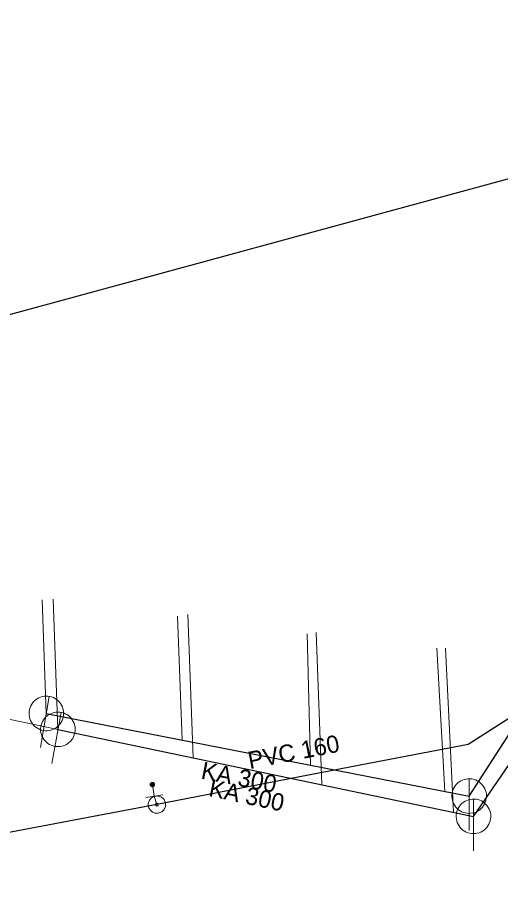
# Model space of a CAD drawing. Extents: x -809028 to -807737, y -990545 to -989489.
# Drawn here: x -808702.15 to -808674.21, y -989756.83 to -989706.95 of the extents above; entities that cross this region are included whole.
import ezdxf

# ---------------------------------------------------------------- set-up
doc = ezdxf.new("R2010")
doc.units = 0
doc.header["$LTSCALE"] = 0.32
for name, color, linetype, lineweight in [('1', 7, 'Continuous', 13), ('11', 7, 'Continuous', 13), ('14', 7, 'Continuous', 25), ('17', 7, 'Continuous', 25), ('22', 7, 'Continuous', 13), ('34', 7, 'Continuous', 13), ('47', 7, 'Continuous', 13), ('9', 7, 'Continuous', 13)]:
    doc.layers.add(name, color=color, linetype=linetype, lineweight=lineweight)

msp = doc.modelspace()

# ---------------------------------------------------------------- linework, layer by layer
at = {"layer": '11'}
for p, q in [((-808700.711, -989740.642), (-808700.473, -989747.21)), ((-808700.082, -989740.607), (-808699.802, -989748.132)), ((-808692.883, -989741.585), (-808692.623, -989748.745)), ((-808692.289, -989741.481), (-808691.978, -989749.77)), ((-808684.881, -989742.529), (-808684.552, -989751.326)), ((-808685.405, -989742.599), (-808685.205, -989750.195)), ((-808677.892, -989743.437), (-808677.437, -989751.714)), ((-808677.403, -989743.437), (-808676.938, -989752.92))]:
    msp.add_line(p, q, dxfattribs=at)
msp.add_lwpolyline([(-808724.563, -989742.664), (-808724.548, -989742.942), (-808699.802, -989748.132)], dxfattribs=at)
at = {"layer": '14'}
for p, q in [((-808676.035, -989751.988), (-808665.723, -989736.017)), ((-808675.783, -989753.162), (-808664.717, -989736.982)), ((-808700.473, -989747.21), (-808676.035, -989751.988)), ((-808699.802, -989748.132), (-808675.783, -989753.162))]:
    msp.add_line(p, q, dxfattribs=at)
at = {"layer": '14', "lineweight": 13}
msp.add_lwpolyline([(-808694.08, -989752.483), (-808694.231, -989751.997), (-808694.34, -989751.322)], dxfattribs=at)
at = {"layer": '17'}
for points in [[(-808462.359, -989745.649), (-808463.609, -989745.59), (-808609.824, -989686.686), (-808669.927, -989715.25), (-808715.085, -989727.543), (-808715.98, -989727.807)], [(-808654.901, -989737.974), (-808658.532, -989739.357), (-808664.09, -989741.73), (-808665.429, -989742.193), (-808676.096, -989748.998), (-808682.329, -989750.202), (-808694.08, -989752.483)], [(-808694.08, -989752.483), (-808714.649, -989756.377), (-808715.958, -989759.501)]]:
    msp.add_lwpolyline(points, dxfattribs=at)
at = {"layer": '22'}
for p, q in [((-808700.802, -989749.183), (-808700.308, -989746.224)), ((-808700.159, -989750.1), (-808699.623, -989747.148)), ((-808676.035, -989753.988), (-808676.034, -989750.988)), ((-808675.783, -989755.162), (-808675.782, -989752.162))]:
    msp.add_line(p, q, dxfattribs=at)
for points in [[(-808699.486, -989747.375), (-808699.474, -989747.266), (-808699.474, -989747.157), (-808699.486, -989747.047), (-808699.509, -989746.941), (-808699.544, -989746.837), (-808699.591, -989746.738), (-808699.648, -989746.644), (-808699.715, -989746.558), (-808699.791, -989746.478), (-808699.874, -989746.409), (-808699.965, -989746.348), (-808700.064, -989746.298), (-808700.166, -989746.259), (-808700.271, -989746.231), (-808700.38, -989746.215), (-808700.489, -989746.211), (-808700.599, -989746.218), (-808700.706, -989746.237), (-808700.811, -989746.269), (-808700.911, -989746.311), (-808701.008, -989746.365), (-808701.096, -989746.428), (-808701.178, -989746.502), (-808701.252, -989746.583), (-808701.315, -989746.672), (-808701.369, -989746.767), (-808701.412, -989746.868), (-808701.444, -989746.973), (-808701.464, -989747.081), (-808701.472, -989747.19), (-808701.469, -989747.299), (-808701.452, -989747.407), (-808701.426, -989747.513), (-808701.387, -989747.616), (-808701.336, -989747.713), (-808701.277, -989747.805), (-808701.207, -989747.889), (-808701.128, -989747.965), (-808701.042, -989748.032), (-808700.948, -989748.09), (-808700.85, -989748.137), (-808700.746, -989748.172), (-808700.638, -989748.196), (-808700.53, -989748.208), (-808700.42, -989748.208), (-808700.312, -989748.197), (-808700.205, -989748.173), (-808700.101, -989748.138), (-808700.002, -989748.092), (-808699.908, -989748.035), (-808699.821, -989747.969), (-808699.742, -989747.893), (-808699.671, -989747.809), (-808699.612, -989747.718), (-808699.561, -989747.621), (-808699.521, -989747.518), (-808699.494, -989747.412)], [(-808698.818, -989748.311), (-808698.804, -989748.202), (-808698.803, -989748.093), (-808698.813, -989747.983), (-808698.834, -989747.877), (-808698.868, -989747.772), (-808698.913, -989747.672), (-808698.969, -989747.578), (-808699.035, -989747.491), (-808699.109, -989747.41), (-808699.192, -989747.339), (-808699.282, -989747.277), (-808699.38, -989747.226), (-808699.481, -989747.185), (-808699.587, -989747.156), (-808699.695, -989747.138), (-808699.804, -989747.132), (-808699.914, -989747.138), (-808700.022, -989747.156), (-808700.127, -989747.187), (-808700.228, -989747.227), (-808700.325, -989747.28), (-808700.414, -989747.342), (-808700.497, -989747.414), (-808700.572, -989747.494), (-808700.637, -989747.582), (-808700.692, -989747.677), (-808700.736, -989747.777), (-808700.769, -989747.881), (-808700.791, -989747.989), (-808700.801, -989748.098), (-808700.799, -989748.207), (-808700.784, -989748.315), (-808700.759, -989748.422), (-808700.722, -989748.525), (-808700.672, -989748.623), (-808700.614, -989748.715), (-808700.545, -989748.801), (-808700.468, -989748.878), (-808700.382, -989748.946), (-808700.289, -989749.005), (-808700.191, -989749.053), (-808700.088, -989749.09), (-808699.981, -989749.116), (-808699.873, -989749.129), (-808699.763, -989749.131), (-808699.655, -989749.121), (-808699.547, -989749.099), (-808699.443, -989749.065), (-808699.343, -989749.02), (-808699.249, -989748.965), (-808699.161, -989748.9), (-808699.081, -989748.825), (-808699.009, -989748.742), (-808698.948, -989748.652), (-808698.896, -989748.556), (-808698.855, -989748.453), (-808698.825, -989748.348)], [(-808675.035, -989751.988), (-808675.04, -989751.879), (-808675.058, -989751.771), (-808675.088, -989751.665), (-808675.128, -989751.564), (-808675.18, -989751.467), (-808675.242, -989751.377), (-808675.314, -989751.294), (-808675.394, -989751.22), (-808675.482, -989751.154), (-808675.576, -989751.099), (-808675.676, -989751.054), (-808675.781, -989751.021), (-808675.888, -989750.999), (-808675.997, -989750.989), (-808676.107, -989750.991), (-808676.215, -989751.005), (-808676.322, -989751.03), (-808676.425, -989751.067), (-808676.523, -989751.116), (-808676.615, -989751.174), (-808676.701, -989751.243), (-808676.778, -989751.32), (-808676.847, -989751.406), (-808676.906, -989751.498), (-808676.954, -989751.596), (-808676.991, -989751.699), (-808677.017, -989751.806), (-808677.031, -989751.914), (-808677.034, -989752.024), (-808677.024, -989752.133), (-808677.003, -989752.24), (-808676.969, -989752.344), (-808676.925, -989752.444), (-808676.87, -989752.539), (-808676.804, -989752.627), (-808676.73, -989752.707), (-808676.647, -989752.779), (-808676.557, -989752.841), (-808676.461, -989752.893), (-808676.359, -989752.934), (-808676.254, -989752.964), (-808676.146, -989752.982), (-808676.036, -989752.988), (-808675.927, -989752.982), (-808675.819, -989752.964), (-808675.714, -989752.935), (-808675.612, -989752.894), (-808675.515, -989752.842), (-808675.425, -989752.78), (-808675.342, -989752.709), (-808675.267, -989752.629), (-808675.202, -989752.541), (-808675.146, -989752.447), (-808675.102, -989752.347), (-808675.068, -989752.243), (-808675.046, -989752.135), (-808675.036, -989752.026)], [(-808674.783, -989753.162), (-808674.788, -989753.053), (-808674.806, -989752.945), (-808674.836, -989752.839), (-808674.876, -989752.738), (-808674.928, -989752.641), (-808674.99, -989752.551), (-808675.062, -989752.468), (-808675.142, -989752.394), (-808675.23, -989752.328), (-808675.324, -989752.273), (-808675.424, -989752.228), (-808675.529, -989752.195), (-808675.636, -989752.173), (-808675.745, -989752.163), (-808675.855, -989752.165), (-808675.963, -989752.179), (-808676.07, -989752.204), (-808676.173, -989752.241), (-808676.271, -989752.29), (-808676.363, -989752.348), (-808676.449, -989752.417), (-808676.526, -989752.494), (-808676.595, -989752.58), (-808676.654, -989752.672), (-808676.702, -989752.77), (-808676.739, -989752.873), (-808676.765, -989752.98), (-808676.779, -989753.088), (-808676.782, -989753.198), (-808676.772, -989753.307), (-808676.751, -989753.414), (-808676.717, -989753.518), (-808676.673, -989753.618), (-808676.618, -989753.713), (-808676.552, -989753.801), (-808676.478, -989753.881), (-808676.395, -989753.953), (-808676.305, -989754.015), (-808676.209, -989754.067), (-808676.107, -989754.108), (-808676.002, -989754.138), (-808675.894, -989754.156), (-808675.784, -989754.162), (-808675.675, -989754.156), (-808675.567, -989754.138), (-808675.462, -989754.109), (-808675.36, -989754.068), (-808675.263, -989754.016), (-808675.173, -989753.954), (-808675.09, -989753.883), (-808675.015, -989753.803), (-808674.95, -989753.715), (-808674.894, -989753.621), (-808674.85, -989753.521), (-808674.816, -989753.417), (-808674.794, -989753.309), (-808674.784, -989753.2)]]:
    msp.add_lwpolyline(points, close=True, dxfattribs=at)
at = {"layer": '34'}
msp.add_line((-808693.737, -989751.916), (-808694.724, -989752.076), dxfattribs=at)
at = {"layer": '47'}
for points in [[(-808693.589, -989752.387), (-808693.602, -989752.337), (-808693.619, -989752.287), (-808693.643, -989752.241), (-808693.67, -989752.196), (-808693.702, -989752.155), (-808693.739, -989752.117), (-808693.779, -989752.084), (-808693.822, -989752.055), (-808693.868, -989752.03), (-808693.917, -989752.01), (-808693.967, -989751.995), (-808694.019, -989751.987), (-808694.071, -989751.983), (-808694.123, -989751.985), (-808694.175, -989751.992), (-808694.225, -989752.005), (-808694.275, -989752.022), (-808694.322, -989752.046), (-808694.366, -989752.073), (-808694.407, -989752.105), (-808694.445, -989752.142), (-808694.479, -989752.182), (-808694.508, -989752.226), (-808694.533, -989752.271), (-808694.552, -989752.32), (-808694.567, -989752.37), (-808694.576, -989752.422), (-808694.579, -989752.474), (-808694.577, -989752.526), (-808694.57, -989752.578), (-808694.557, -989752.628), (-808694.54, -989752.678), (-808694.517, -989752.725), (-808694.489, -989752.769), (-808694.457, -989752.81), (-808694.421, -989752.848), (-808694.381, -989752.882), (-808694.337, -989752.912), (-808694.291, -989752.936), (-808694.242, -989752.955), (-808694.192, -989752.97), (-808694.141, -989752.979), (-808694.088, -989752.982), (-808694.036, -989752.98), (-808693.984, -989752.973), (-808693.934, -989752.96), (-808693.884, -989752.943), (-808693.838, -989752.92), (-808693.793, -989752.892), (-808693.752, -989752.86), (-808693.714, -989752.824), (-808693.681, -989752.784), (-808693.651, -989752.741), (-808693.627, -989752.694), (-808693.607, -989752.645), (-808693.592, -989752.595), (-808693.584, -989752.544), (-808693.58, -989752.491), (-808693.582, -989752.439)], [(-808693.999, -989752.467), (-808694.001, -989752.458), (-808694.004, -989752.451), (-808694.008, -989752.443), (-808694.012, -989752.436), (-808694.018, -989752.429), (-808694.024, -989752.423), (-808694.03, -989752.417), (-808694.037, -989752.412), (-808694.045, -989752.409), (-808694.053, -989752.405), (-808694.061, -989752.403), (-808694.07, -989752.401), (-808694.078, -989752.401), (-808694.086, -989752.4), (-808694.095, -989752.402), (-808694.104, -989752.404), (-808694.111, -989752.407), (-808694.119, -989752.411), (-808694.126, -989752.415), (-808694.133, -989752.421), (-808694.139, -989752.427), (-808694.145, -989752.433), (-808694.15, -989752.44), (-808694.154, -989752.448), (-808694.157, -989752.456), (-808694.159, -989752.464), (-808694.161, -989752.473), (-808694.161, -989752.481), (-808694.162, -989752.489), (-808694.16, -989752.498), (-808694.158, -989752.507), (-808694.155, -989752.514), (-808694.151, -989752.522), (-808694.147, -989752.529), (-808694.141, -989752.536), (-808694.136, -989752.542), (-808694.129, -989752.548), (-808694.122, -989752.553), (-808694.114, -989752.557), (-808694.106, -989752.56), (-808694.098, -989752.562), (-808694.089, -989752.564), (-808694.081, -989752.564), (-808694.073, -989752.565), (-808694.064, -989752.563), (-808694.055, -989752.561), (-808694.048, -989752.558), (-808694.04, -989752.554), (-808694.033, -989752.55), (-808694.026, -989752.544), (-808694.02, -989752.539), (-808694.014, -989752.532), (-808694.009, -989752.525), (-808694.006, -989752.517), (-808694.002, -989752.509), (-808694, -989752.501), (-808693.998, -989752.492), (-808693.998, -989752.484), (-808693.997, -989752.476)]]:
    msp.add_lwpolyline(points, close=True, dxfattribs=at)
at = {"layer": '9'}
for points in [[(-808694.466, -989751.322), (-808694.466, -989751.335), (-808694.463, -989751.348), (-808694.461, -989751.361), (-808694.456, -989751.373), (-808694.45, -989751.385), (-808694.443, -989751.396), (-808694.434, -989751.406), (-808694.424, -989751.416), (-808694.414, -989751.424), (-808694.404, -989751.431), (-808694.392, -989751.437), (-808694.38, -989751.442), (-808694.367, -989751.445), (-808694.353, -989751.447), (-808694.341, -989751.449), (-808694.328, -989751.448), (-808694.315, -989751.446), (-808694.302, -989751.443), (-808694.289, -989751.438), (-808694.277, -989751.432), (-808694.267, -989751.425), (-808694.257, -989751.417), (-808694.247, -989751.407), (-808694.239, -989751.397), (-808694.232, -989751.386), (-808694.226, -989751.374), (-808694.221, -989751.362), (-808694.218, -989751.349), (-808694.216, -989751.336), (-808694.213, -989751.323), (-808694.215, -989751.31), (-808694.217, -989751.297), (-808694.22, -989751.284), (-808694.225, -989751.272), (-808694.23, -989751.26), (-808694.238, -989751.249), (-808694.245, -989751.239), (-808694.255, -989751.229), (-808694.266, -989751.221), (-808694.277, -989751.214), (-808694.289, -989751.208), (-808694.301, -989751.203), (-808694.314, -989751.2), (-808694.326, -989751.198), (-808694.34, -989751.197), (-808694.353, -989751.197), (-808694.365, -989751.199), (-808694.379, -989751.202), (-808694.391, -989751.207), (-808694.402, -989751.213), (-808694.414, -989751.22), (-808694.424, -989751.228), (-808694.434, -989751.238), (-808694.441, -989751.248), (-808694.449, -989751.259), (-808694.455, -989751.271), (-808694.46, -989751.283), (-808694.463, -989751.296), (-808694.465, -989751.309)], [(-808694.446, -989751.322), (-808694.446, -989751.333), (-808694.445, -989751.344), (-808694.441, -989751.355), (-808694.438, -989751.365), (-808694.433, -989751.375), (-808694.427, -989751.384), (-808694.419, -989751.393), (-808694.412, -989751.401), (-808694.402, -989751.408), (-808694.394, -989751.414), (-808694.384, -989751.419), (-808694.374, -989751.423), (-808694.363, -989751.426), (-808694.352, -989751.429), (-808694.341, -989751.429), (-808694.33, -989751.429), (-808694.319, -989751.427), (-808694.308, -989751.424), (-808694.298, -989751.42), (-808694.288, -989751.415), (-808694.279, -989751.409), (-808694.27, -989751.402), (-808694.262, -989751.394), (-808694.255, -989751.385), (-808694.249, -989751.376), (-808694.244, -989751.366), (-808694.24, -989751.356), (-808694.237, -989751.345), (-808694.235, -989751.334), (-808694.233, -989751.323), (-808694.233, -989751.312), (-808694.235, -989751.301), (-808694.239, -989751.29), (-808694.243, -989751.28), (-808694.248, -989751.27), (-808694.254, -989751.261), (-808694.261, -989751.252), (-808694.269, -989751.244), (-808694.277, -989751.237), (-808694.287, -989751.231), (-808694.297, -989751.226), (-808694.306, -989751.222), (-808694.318, -989751.219), (-808694.328, -989751.217), (-808694.34, -989751.217), (-808694.351, -989751.216), (-808694.362, -989751.218), (-808694.373, -989751.221), (-808694.382, -989751.225), (-808694.392, -989751.23), (-808694.402, -989751.236), (-808694.411, -989751.243), (-808694.419, -989751.251), (-808694.426, -989751.26), (-808694.431, -989751.269), (-808694.436, -989751.279), (-808694.441, -989751.289), (-808694.444, -989751.3), (-808694.446, -989751.311)], [(-808694.427, -989751.322), (-808694.427, -989751.331), (-808694.426, -989751.34), (-808694.423, -989751.349), (-808694.419, -989751.357), (-808694.416, -989751.365), (-808694.411, -989751.373), (-808694.404, -989751.38), (-808694.399, -989751.386), (-808694.392, -989751.392), (-808694.384, -989751.397), (-808694.375, -989751.401), (-808694.368, -989751.404), (-808694.358, -989751.407), (-808694.35, -989751.408), (-808694.341, -989751.41), (-808694.331, -989751.409), (-808694.323, -989751.408), (-808694.314, -989751.405), (-808694.306, -989751.402), (-808694.298, -989751.398), (-808694.289, -989751.393), (-808694.282, -989751.387), (-808694.277, -989751.381), (-808694.271, -989751.374), (-808694.266, -989751.366), (-808694.262, -989751.358), (-808694.259, -989751.35), (-808694.255, -989751.341), (-808694.255, -989751.332), (-808694.252, -989751.323), (-808694.254, -989751.314), (-808694.255, -989751.305), (-808694.257, -989751.296), (-808694.261, -989751.288), (-808694.265, -989751.28), (-808694.27, -989751.272), (-808694.276, -989751.265), (-808694.282, -989751.259), (-808694.289, -989751.253), (-808694.297, -989751.248), (-808694.304, -989751.244), (-808694.313, -989751.241), (-808694.321, -989751.238), (-808694.331, -989751.237), (-808694.34, -989751.236), (-808694.348, -989751.236), (-808694.358, -989751.237), (-808694.367, -989751.24), (-808694.375, -989751.243), (-808694.382, -989751.247), (-808694.391, -989751.252), (-808694.397, -989751.258), (-808694.404, -989751.264), (-808694.409, -989751.271), (-808694.414, -989751.279), (-808694.419, -989751.287), (-808694.422, -989751.295), (-808694.424, -989751.304), (-808694.426, -989751.313)], [(-808694.407, -989751.322), (-808694.407, -989751.329), (-808694.406, -989751.336), (-808694.404, -989751.343), (-808694.402, -989751.349), (-808694.399, -989751.355), (-808694.395, -989751.361), (-808694.391, -989751.367), (-808694.386, -989751.372), (-808694.38, -989751.376), (-808694.374, -989751.38), (-808694.368, -989751.383), (-808694.362, -989751.386), (-808694.355, -989751.387), (-808694.348, -989751.39), (-808694.341, -989751.39), (-808694.333, -989751.39), (-808694.326, -989751.388), (-808694.32, -989751.387), (-808694.314, -989751.384), (-808694.306, -989751.381), (-808694.302, -989751.377), (-808694.296, -989751.373), (-808694.291, -989751.368), (-808694.287, -989751.362), (-808694.282, -989751.356), (-808694.279, -989751.35), (-808694.277, -989751.344), (-808694.275, -989751.337), (-808694.274, -989751.33), (-808694.272, -989751.323), (-808694.272, -989751.316), (-808694.274, -989751.309), (-808694.276, -989751.302), (-808694.279, -989751.296), (-808694.282, -989751.289), (-808694.286, -989751.284), (-808694.289, -989751.278), (-808694.294, -989751.273), (-808694.301, -989751.269), (-808694.306, -989751.265), (-808694.313, -989751.262), (-808694.319, -989751.259), (-808694.326, -989751.257), (-808694.333, -989751.256), (-808694.34, -989751.256), (-808694.347, -989751.256), (-808694.353, -989751.256), (-808694.36, -989751.258), (-808694.367, -989751.261), (-808694.373, -989751.264), (-808694.379, -989751.268), (-808694.385, -989751.272), (-808694.39, -989751.277), (-808694.394, -989751.283), (-808694.397, -989751.288), (-808694.401, -989751.295), (-808694.404, -989751.301), (-808694.404, -989751.308), (-808694.407, -989751.315)], [(-808694.387, -989751.322), (-808694.387, -989751.327), (-808694.387, -989751.332), (-808694.386, -989751.337), (-808694.384, -989751.341), (-808694.382, -989751.346), (-808694.379, -989751.35), (-808694.375, -989751.353), (-808694.372, -989751.357), (-808694.369, -989751.36), (-808694.365, -989751.363), (-808694.36, -989751.365), (-808694.355, -989751.367), (-808694.351, -989751.368), (-808694.346, -989751.37), (-808694.341, -989751.37), (-808694.336, -989751.37), (-808694.331, -989751.369), (-808694.326, -989751.368), (-808694.321, -989751.366), (-808694.316, -989751.364), (-808694.313, -989751.361), (-808694.309, -989751.358), (-808694.306, -989751.354), (-808694.303, -989751.351), (-808694.299, -989751.347), (-808694.298, -989751.342), (-808694.296, -989751.338), (-808694.294, -989751.333), (-808694.294, -989751.328), (-808694.293, -989751.323), (-808694.293, -989751.318), (-808694.294, -989751.313), (-808694.294, -989751.308), (-808694.297, -989751.304), (-808694.299, -989751.299), (-808694.302, -989751.295), (-808694.304, -989751.291), (-808694.308, -989751.288), (-808694.311, -989751.285), (-808694.316, -989751.282), (-808694.321, -989751.28), (-808694.325, -989751.278), (-808694.33, -989751.277), (-808694.335, -989751.276), (-808694.34, -989751.276), (-808694.345, -989751.276), (-808694.35, -989751.277), (-808694.355, -989751.277), (-808694.358, -989751.279), (-808694.364, -989751.281), (-808694.368, -989751.284), (-808694.37, -989751.287), (-808694.375, -989751.29), (-808694.377, -989751.294), (-808694.38, -989751.298), (-808694.382, -989751.303), (-808694.385, -989751.307), (-808694.386, -989751.312), (-808694.387, -989751.317)], [(-808694.367, -989751.322), (-808694.367, -989751.325), (-808694.368, -989751.328), (-808694.367, -989751.33), (-808694.365, -989751.333), (-808694.365, -989751.336), (-808694.363, -989751.338), (-808694.36, -989751.34), (-808694.358, -989751.342), (-808694.357, -989751.344), (-808694.355, -989751.346), (-808694.352, -989751.348), (-808694.348, -989751.349), (-808694.347, -989751.349), (-808694.343, -989751.35), (-808694.341, -989751.35), (-808694.338, -989751.35), (-808694.335, -989751.35), (-808694.331, -989751.349), (-808694.33, -989751.348), (-808694.326, -989751.347), (-808694.325, -989751.345), (-808694.321, -989751.343), (-808694.32, -989751.341), (-808694.319, -989751.339), (-808694.316, -989751.337), (-808694.316, -989751.334), (-808694.314, -989751.331), (-808694.314, -989751.329), (-808694.313, -989751.326), (-808694.311, -989751.323), (-808694.313, -989751.32), (-808694.313, -989751.317), (-808694.314, -989751.314), (-808694.315, -989751.312), (-808694.316, -989751.309), (-808694.318, -989751.307), (-808694.319, -989751.304), (-808694.321, -989751.302), (-808694.324, -989751.301), (-808694.326, -989751.299), (-808694.328, -989751.298), (-808694.331, -989751.297), (-808694.333, -989751.296), (-808694.337, -989751.296), (-808694.34, -989751.295), (-808694.343, -989751.296), (-808694.346, -989751.295), (-808694.348, -989751.297), (-808694.351, -989751.297), (-808694.353, -989751.298), (-808694.355, -989751.3), (-808694.358, -989751.301), (-808694.36, -989751.303), (-808694.362, -989751.306), (-808694.364, -989751.308), (-808694.365, -989751.311), (-808694.365, -989751.313), (-808694.367, -989751.316), (-808694.367, -989751.319)], [(-808694.348, -989751.322), (-808694.348, -989751.324), (-808694.348, -989751.324), (-808694.347, -989751.324), (-808694.347, -989751.326), (-808694.348, -989751.327), (-808694.346, -989751.327), (-808694.346, -989751.327), (-808694.346, -989751.329), (-808694.346, -989751.329), (-808694.345, -989751.33), (-808694.343, -989751.33), (-808694.343, -989751.33), (-808694.343, -989751.331), (-808694.341, -989751.331), (-808694.341, -989751.331), (-808694.34, -989751.331), (-808694.338, -989751.331), (-808694.338, -989751.33), (-808694.338, -989751.33), (-808694.336, -989751.33), (-808694.336, -989751.329), (-808694.336, -989751.329), (-808694.335, -989751.328), (-808694.335, -989751.328), (-808694.333, -989751.327), (-808694.333, -989751.326), (-808694.331, -989751.325), (-808694.331, -989751.325), (-808694.331, -989751.324), (-808694.331, -989751.323), (-808694.331, -989751.322), (-808694.331, -989751.321), (-808694.331, -989751.321), (-808694.333, -989751.32), (-808694.333, -989751.319), (-808694.333, -989751.318), (-808694.333, -989751.318), (-808694.335, -989751.317), (-808694.335, -989751.317), (-808694.336, -989751.316), (-808694.337, -989751.316), (-808694.338, -989751.315), (-808694.338, -989751.315), (-808694.338, -989751.315), (-808694.34, -989751.315), (-808694.341, -989751.315), (-808694.342, -989751.315), (-808694.342, -989751.315), (-808694.343, -989751.316), (-808694.343, -989751.315), (-808694.345, -989751.317), (-808694.345, -989751.317), (-808694.346, -989751.317), (-808694.346, -989751.317), (-808694.347, -989751.319), (-808694.347, -989751.32), (-808694.347, -989751.321), (-808694.348, -989751.321), (-808694.348, -989751.322)]]:
    msp.add_lwpolyline(points, close=True, dxfattribs=at)

# ---------------------------------------------------------------- texts
at = {"layer": '1'}
for s, rotation, p in [('PVC 160 ', 11, (-808688.711, -989750.434)), ('KA 300', 349, (-808691.579, -989750.971)), ('KA 300', 348, (-808691.135, -989751.975))]:
    msp.add_text(s, height=1, rotation=rotation, dxfattribs=at).set_placement(p)

doc.saveas('drawing.dxf')
